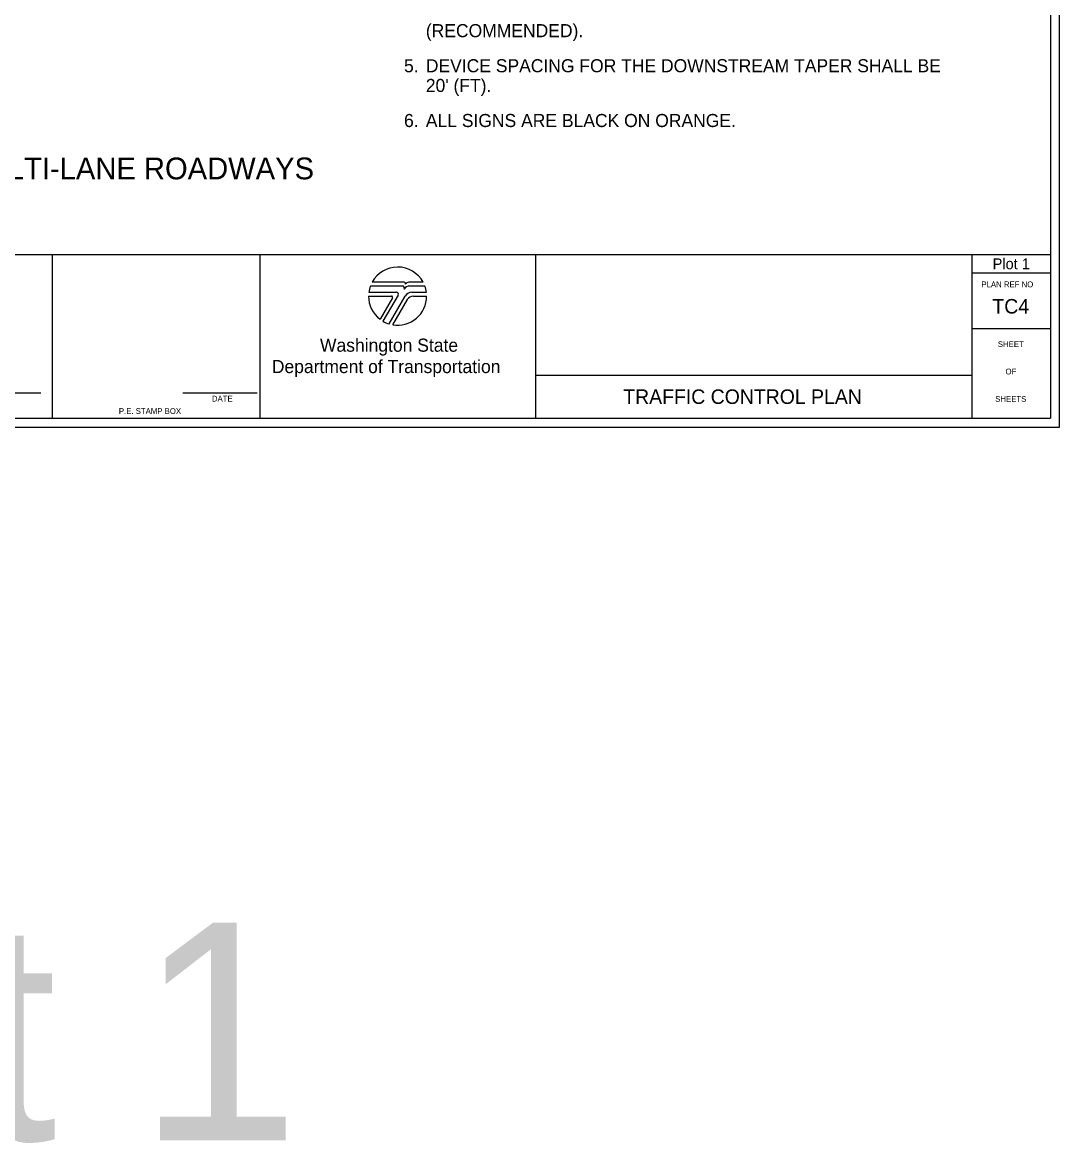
# Model space of a CAD drawing. Extents: x 99988 to 100172, y 99995 to 100047.
# Drawn here: x 100008.68 to 100015.81, y 99995.01 to 100002.72 of the extents above; entities that cross this region are included whole.
import ezdxf

# ---------------------------------------------------------------- set-up
doc = ezdxf.new("R2010")
doc.units = 0
for name, color, linetype in [('SH_DE_DetailBody1Text', 7, 'Continuous'), ('SH_DE_DetailHeading1Text', 7, 'Continuous'), ('SH_GI_PlotLimits', 7, 'Continuous'), ('SH_GI_SheetBorder', 7, 'Continuous'), ('SH_GI_SheetLocationText', 7, 'Continuous'), ('SH_GI_SheetTextInCells', 7, 'Continuous'), ('SH_GI_TitleBlockText', 7, 'Continuous'), ('SH_GI_WSDOTLogo', 7, 'Continuous')]:
    doc.layers.add(name, color=color, linetype=linetype)

msp = doc.modelspace()

# ---------------------------------------------------------------- linework, layer by layer
at = {"layer": 'SH_GI_PlotLimits'}
msp.add_lwpolyline([(99999.3125, 99999.9375), (100015.8125, 99999.9375), (100015.8125, 100010.4375), (99999.3125, 100010.4375)], close=True, dxfattribs=at)
at = {"layer": 'SH_GI_SheetBorder'}
for p, q in [((100015.75, 100010.375), (100015.75, 100000)), ((100000, 100001.1259), (100015.75, 100001.1259)), ((100008.8828, 100000), (100008.8828, 100001.1259)), ((100010.3089, 100001.1259), (100010.3089, 100000)), ((100012.2055, 100001.1259), (100012.2055, 100000)), ((100015.2079, 100001.1259), (100015.2079, 100000)), ((100015.2079, 100001.0008), (100015.75, 100001.0008)), ((100015.2079, 100000.6176), (100015.75, 100000.6176)), ((100012.2055, 100000.2955), (100015.2079, 100000.2955)), ((100008.2903, 100000.1733), (100008.802, 100000.1733)), ((100009.7797, 100000.1733), (100010.2914, 100000.1733)), ((100000, 100000), (100015.75, 100000))]:
    msp.add_line(p, q, dxfattribs=at)
at = {"layer": 'SH_GI_WSDOTLogo'}
for p, q in [((100011.2894, 100000.9094), (100011.0697, 100000.9094)), ((100011.303, 100000.9354), (100011.0815, 100000.9354)), ((100011.433, 100000.9354), (100011.3351, 100000.9354)), ((100011.343, 100000.9094), (100011.3429, 100000.9094)), ((100011.4448, 100000.9094), (100011.343, 100000.9094)), ((100011.0572, 100000.84), (100011.2148, 100000.84)), ((100011.059, 100000.8661), (100011.2496, 100000.8661)), ((100011.222, 100000.8277), (100011.1364, 100000.6807)), ((100011.261, 100000.8464), (100011.1567, 100000.6672)), ((100011.1989, 100000.6487), (100011.3089, 100000.839)), ((100011.2244, 100000.6428), (100011.3242, 100000.8156)), ((100011.3558, 100000.8661), (100011.4555, 100000.8661)), ((100011.3655, 100000.8394), (100011.4572, 100000.8394))]:
    msp.add_line(p, q, dxfattribs=at)
for centre, radius, start, end in [((100011.2572, 100000.84), 0.2, 28.47865, 151.53204), ((100011.2572, 100000.84), 0.2, 159.69598, 172.50569), ((100011.2894, 100000.8946), 0.0148, 327.8418, 89.99855), ((100011.3429, 100000.861), 0.0484, 89.99529, 147.82376), ((100011.303, 100000.9263), 0.00903, 329.87418, 90.00328), ((100011.3352, 100000.9066), 0.0287, 90.00721, 148.16763), ((100011.2572, 100000.84), 0.2, 7.49431, 20.29406), ((100011.2572, 100000.84), 0.2, 179.99864, 232.84327), ((100011.2149, 100000.8318), 0.0082, 329.74356, 90), ((100011.2572, 100000.84), 0.2, 260.54554, 359.80857), ((100011.2497, 100000.853), 0.0131, 329.76834, 90), ((100011.3558, 100000.8119), 0.0542, 90, 149.99738), ((100011.3654, 100000.7918), 0.0476, 90, 150.05432), ((100011.2572, 100000.84), 0.2, 239.79292, 253.0448)]:
    msp.add_arc(centre, radius, start, end, dxfattribs=at)

# ---------------------------------------------------------------- texts
at = {"layer": 'SH_DE_DetailBody1Text'}
for s, p in [('(RECOMMENDED).', (100011.4515, 100002.6226)), ('5.', (100011.3015, 100002.3811)), ('DEVICE SPACING FOR THE DOWNSTREAM TAPER SHALL BE', (100011.4515, 100002.3811)), ("20' (FT).", (100011.4515, 100002.2454)), ('6.', (100011.3015, 100002.004)), ('ALL SIGNS ARE BLACK ON ORANGE.', (100011.4515, 100002.004))]:
    msp.add_text(s, height=0.09, dxfattribs=at).set_placement(p)
at = {"layer": 'SH_DE_DetailHeading1Text'}
msp.add_text('DOUBLE-LANE CLOSURE FOR MULTI-LANE ROADWAYS', height=0.15, dxfattribs=at).set_placement((100005.2875, 100001.644))
at = {"layer": 'SH_GI_SheetBorder'}
msp.add_text('PLAN REF NO', height=0.040032, dxfattribs=at).set_placement((100015.2747, 100000.9008))
at = {"layer": 'SH_GI_SheetLocationText'}
for height, p in [(0.075, (100015.3518, 100001.025)), (1.5, (100005.4547, 99995.0267))]:
    msp.add_text('Plot 1', height=height, dxfattribs=at).set_placement(p)
at = {"layer": 'SH_GI_SheetTextInCells'}
for s, height, p in [('Washington State', 0.090072, (100010.7229, 100000.4571)), ('SHEET', 0.04003, (100015.3877, 100000.4896)), ('Department of Transportation', 0.090072, (100010.3916, 100000.3101)), ('OF', 0.04003, (100015.4406, 100000.3008)), ('DATE', 0.04003, (100009.9794, 100000.1141)), ('SHEETS', 0.04003, (100015.3698, 100000.112)), ('P.E. STAMP BOX', 0.040032, (100009.339, 100000.0286))]:
    msp.add_text(s, height=height, dxfattribs=at).set_placement(p)
at = {"layer": 'SH_GI_TitleBlockText'}
for s, p in [('TC4', (100015.3502, 100000.72)), ('TRAFFIC CONTROL PLAN', (100012.8099, 100000.0977))]:
    msp.add_text(s, height=0.1, dxfattribs=at).set_placement(p)

doc.saveas('drawing.dxf')
